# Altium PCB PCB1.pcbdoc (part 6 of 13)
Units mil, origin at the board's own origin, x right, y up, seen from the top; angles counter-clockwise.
Board outline 5895.51 x 5895.51 mil, 8 copper layers (Top Layer, L2_GND1, L3_SIG1, L4_GND2, L5_PWR, L6_SIG2, L7_GND3, Bottom Layer), stack 63.761 mil thick; 673 components, 558 nets, 2797 pads, 1861 vias.
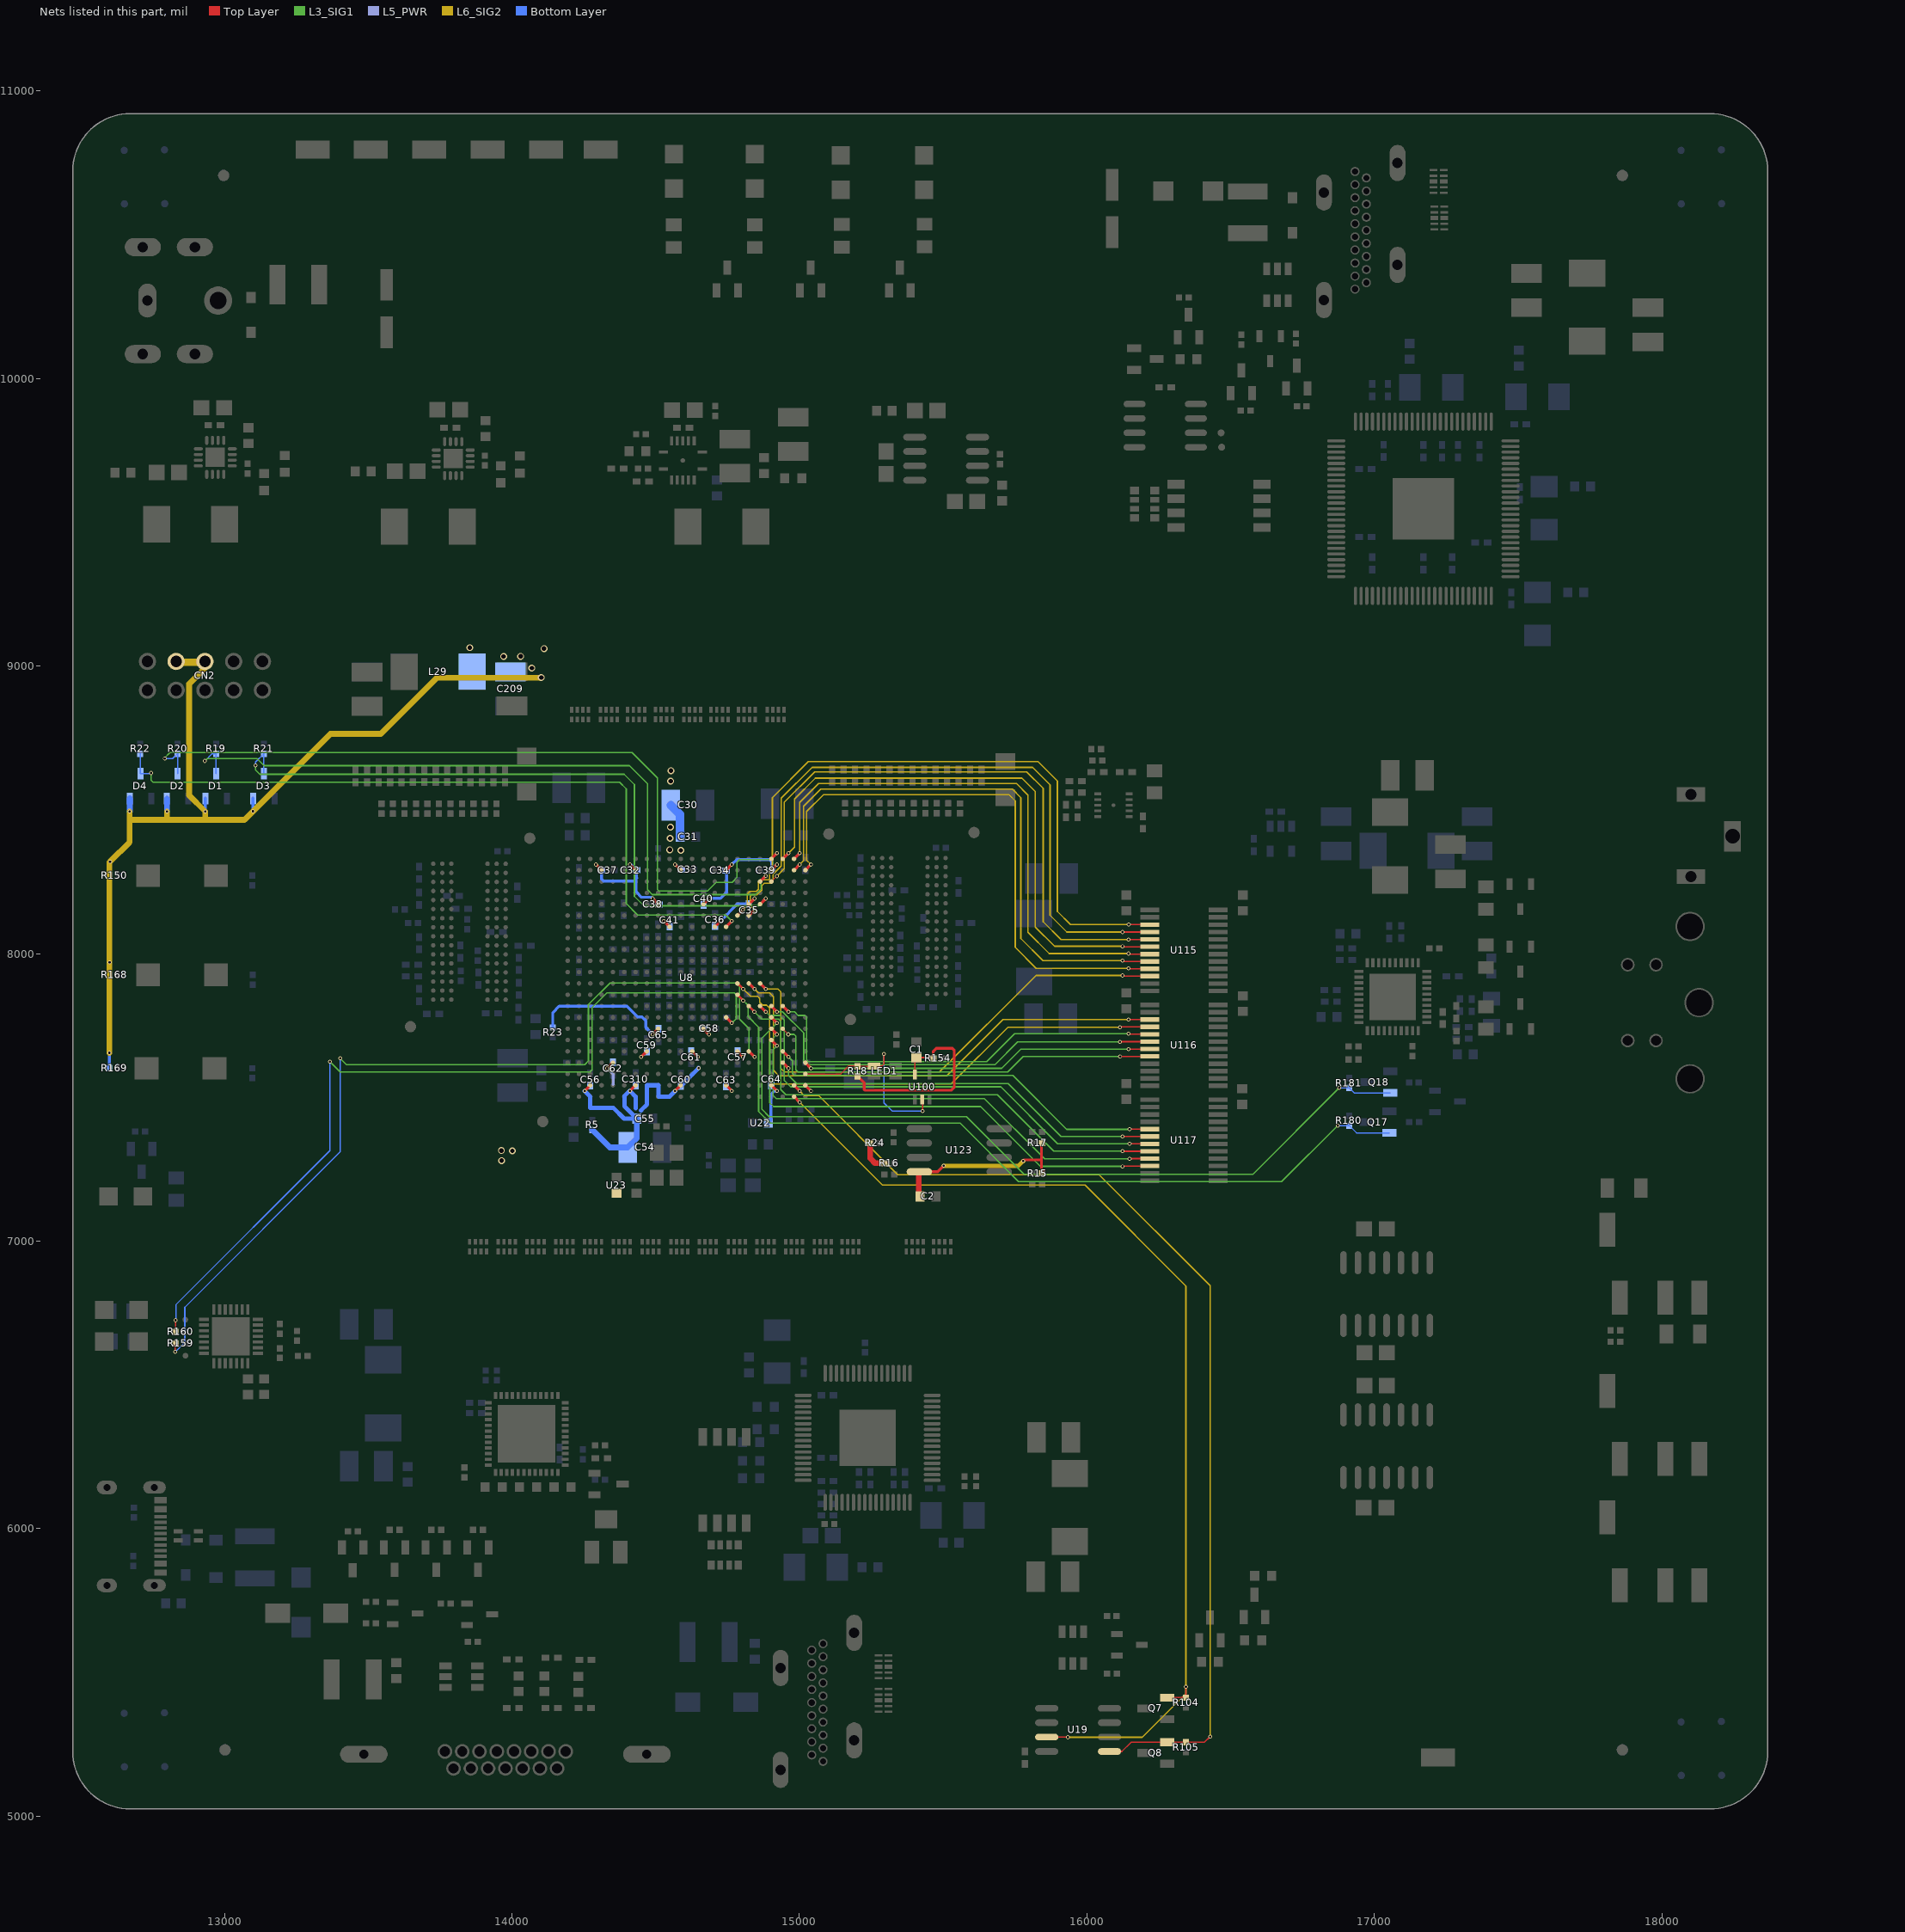
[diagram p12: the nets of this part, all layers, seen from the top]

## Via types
v1: diameter 23.62, hole 15.75, Top Layer to Bottom Layer, 621 vias
v2: diameter 13.8, hole 7.9, Top Layer to Bottom Layer, 567 vias
v3: diameter 13.78, hole 7.87, Top Layer to Bottom Layer, 529 vias
v4: diameter 13.78, hole 7.9, Top Layer to Bottom Layer, 114 vias
v5: diameter 15.75, hole 7.87, Top Layer to Bottom Layer, 16 vias
v6: diameter 24, hole 12, Top Layer to Bottom Layer, 10 vias
v7: diameter 11.81, hole 7.87, Top Layer to Bottom Layer, 4 vias

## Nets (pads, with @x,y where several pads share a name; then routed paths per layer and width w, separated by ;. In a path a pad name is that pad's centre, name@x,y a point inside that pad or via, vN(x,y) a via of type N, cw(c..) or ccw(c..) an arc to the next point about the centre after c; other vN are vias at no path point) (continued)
FPGA_3V3: C1.2 C2.2 C30.2 C31.2 C32.2 C33.2 C34.2 C35.2 C36.2 C37.2 C38.2 C39.2 C40.2 C41.2 C54.2 C55.2 C56.2 C57.2 C58.2 C59.2 C60.2 C61.2 C62.2 C63.2 C64.2 C65.2 C209.2 C310.2 CN2.4 CN2.6 D1.2 D2.2 D3.2 D4.2 L29.2 R5.2 R15.2 R16.2 R17.2 R18.1 R23.2 R24.2 R150.2 R154.1 R168.2 R169.2 U8.AA3 U8.AA7 U8.AA11 U8.AA15 U8.AA19 U8.AA22 U8.B4 U8.B7 U8.B11 U8.B15 U8.B19 U8.E9 U8.E13 U8.E17 U8.G10 U8.G14 U8.T9 U8.T13 U8.V8 U8.V12 U8.V16 U8.W5 U22.1 U23.1 U100.5 U123.8 | length 8780.3
  Top Layer w4.7: U100.5@15401.77,7579.31 15401.77,7632.85 C1.2@15407.36,7638.44 15462.88,7638.44 R154.1@15465.32,7636
  Top Layer w10: v2(14253.04,7522.32) U8.AA3@14272.71,7542 ; v2(14292.41,8309.69) U8.B4@14312.08,8290.01 ; v2(14331.79,7601.05) U8.W5@14351.46,7620.73 ; v2(14410.52,7522.32) U8.AA7@14430.19,7542 ; v2(14410.52,8309.69) U8.B7@14430.19,8290.01 ; v2(14449.89,7640.42) U8.V8@14469.56,7660.1 ; v2(14489.26,7719.16) U8.T9@14508.93,7738.84 ; v2(14489.26,8191.57) U8.E9@14508.93,8171.9 ; v2(14528.63,8112.84) U8.G10@14548.3,8093.16 ; v2(14567.99,7522.32) U8.AA11@14587.66,7542 ; v2(14567.99,8309.69) U8.B11@14587.66,8290.01 ; U8.V12@14627.06,7660.1 v2(14646.74,7640.42) ; U8.T13@14666.41,7738.84 v2(14686.09,7719.16) ; U8.E13@14666.41,8171.9 v2(14686.09,8191.57) ; U8.G14@14705.78,8093.16 v2(14725.46,8112.84) ; U8.AA15@14745.16,7542 v2(14764.84,7522.32) ; U8.B15@14745.16,8290.01 v2(14764.84,8309.69) ; U8.V16@14784.52,7660.1 v2(14804.2,7640.42) ; U8.E17@14823.89,8171.9 v2(14843.57,8191.57) ; U8.AA19@14902.63,7542 v2(14922.31,7522.32) ; U8.B19@14902.63,8290.01 v2(14922.31,8309.69) ; U8.AA22@15020.76,7542 v2(15040.44,7522.32) ; R18.1@15202.36,7573.96 15225.36,7550.96 15225.36,7527 15227.36,7525 15528.36,7525 15538.36,7535 15538.36,7665 15532.36,7671 15476.36,7671 15465.32,7659.96 R154.1@15465.32,7636 ; U123.8@15436.86,7241 15480.58,7241 v3(15501.56,7261.98) ; v3(15778.58,7278.63) 15782.66,7282.72 15842.05,7282.72 ; R15.2@15842.05,7233.31 15842.05,7282.72 ; R17.2@15842.05,7339.55 15842.05,7282.72
  Top Layer w20: R24.2@15246.18,7340.72 15246.18,7288.26 15263.23,7271.21 R16.2@15296.02,7271.21 ; U123.8@15413.41,7236.59 15415.59,7234.41 C2.2@15415.59,7155.27
  L5_PWR w10: v2(14331.79,7601.05) 14352.36,7580.48 14352.36,7545
  L6_SIG2 w15: v3(15501.56,7261.98) 15761.93,7261.98 v3(15778.58,7278.63)
  L6_SIG2 w20: v3(12600.44,7654.73) 12600.44,8317.76 v3(12602.49,8319.81) 12670.62,8387.94 12670.62,8465 ; v3(12670.62,8494.22) 12670.62,8465 ; v3(12800.32,8493.87) 12800.32,8465 ; CN2.6@12932.36,9016 12932.36,9013.28 12932.36,8993 12877.36,8938 12877.36,8550.4 v3(12933.54,8494.22) 12933.54,8465 ; v1(14102.24,8959.68) 13740.04,8959.68 13544.36,8764 13368.88,8764 v3(13099.8,8494.92) 13069.88,8465 12933.54,8465 ; 12670.62,8465 12800.32,8465 ; 12800.32,8465 12933.54,8465
  L6_SIG2 w25: CN2.4@12831.52,9012.62 12832.18,9013.28 12932.36,9013.28 CN2.6@12933.83,9013.28
  Bottom Layer w6: v2(14253.04,7522.32) 14271.22,7540.5 C56.2@14272.62,7540.5 ; v2(14292.41,8309.69) 14294.21,8309.69 C37.2@14312.9,8291 ; v2(14331.79,7601.05) 14331.79,7602.52 C62.2@14350.99,7621.72 ; v2(14410.52,7522.32) 14411.14,7522.32 C310.2@14430.36,7541.54 ; v2(14410.52,8309.69) 14416.13,8309.69 C32.2@14434.82,8291 ; v2(14449.89,7640.42) 14450.24,7640.42 C59.2@14469.36,7659.54 ; v2(14489.26,7719.16) 14508.56,7738.46 C65.2@14509.36,7738.46 ; v2(14489.26,8191.57) 14491.25,8191.57 C38.2@14511.82,8171 ; v2(14528.63,8112.84) 14545.66,8095.81 C41.2@14545.66,8091.87 ; v2(14567.99,7522.32) 14570.32,7522.32 C60.2@14587.91,7539.91 ; v2(14567.99,8309.69) 14571.21,8309.69 C33.2@14588.9,8292 ; C61.2@14623.5,7661.35 14625.81,7661.35 v2(14646.74,7640.42) ; C58.2@14664.9,7737 14668.25,7737 v2(14686.09,7719.16) ; C40.2@14666.73,8169.77 14666.73,8172.22 v2(14686.09,8191.57) ; C36.2@14706.36,8095.54 14708.16,8095.54 v2(14725.46,8112.84) ; C34.2@14746.82,8288 14746.82,8291.67 v2(14764.84,8309.69) ; C63.2@14747.36,7541.54 14764.84,7524.06 v2(14764.84,7522.32) ; C57.2@14783.36,7660.46 14784.16,7660.46 v2(14804.2,7640.42) ; C35.2@14824.46,8172.46 v2(14843.57,8191.57) ; C64.2@14902.36,7541.54 14903.09,7541.54 v2(14922.31,7522.32) ; C39.2@14903.82,8291.2 v2(14922.31,8309.69)
  Bottom Layer w10: v3(12600.44,7654.73) 12600.59,7654.57 R169.2@12600.59,7600.83 ; v3(12600.89,7969.07) 12601.35,7968.61 R168.2@12601.35,7923.85 ; R150.2@12601.79,8270.25 12601.79,8319.11 v3(12602.49,8319.81) ; v3(12933.54,8494.22) 12933.89,8494.57 D1.2@12933.89,8540.62 ; D3.2@13099.1,8540.62 13099.1,8495.63 v3(13099.8,8494.92) ; R23.2@14142.36,7743.04 14142.36,7795 14164.36,7817 14400.36,7817 14437.36,7780 14452.36,7780 14465.36,7767 14465.36,7743.06 v2(14489.26,7719.16) ; C37.2@14311.9,8290 14311.9,8259.46 14319.36,8252 14424.36,8252 14432.25,8259.9 ; C32.2@14434.82,8291 14432.99,8289.18 14432.99,8264.28 14434.82,8262.46 14432.25,8259.9 ; v2(14489.26,8191.57) 14484.83,8196 14450.36,8196 14432.25,8214.1 14432.25,8259.9 ; v2(14686.09,8191.57) 14686.52,8192 14725.36,8192 14746.82,8213.46 C34.2@14746.82,8288 ; v2(14725.46,8112.84) 14725.46,8113.1 14784.82,8172.46 C35.2@14824.36,8172.46 ; v2(14764.84,8309.69) 14782.15,8327 14896.36,8327 14903.82,8319.54 14903.82,8291.2 C39.2@14903.82,8289 ; U22.1@14892.21,7411 14901.36,7420.15 14901.36,7511 14912.68,7522.32 v2(14922.31,7522.32)
  Bottom Layer w15: v2(14253.04,7522.32) 14272.36,7503 14272.36,7464 14352.36,7464 14390.36,7426 C55.2@14434.8,7426 14391.36,7469.44 14391.36,7505 14408.68,7522.32 v2(14410.52,7522.32) 14430.36,7502.48 14430.36,7462 ; 14449.36,7455 14469.36,7475 14469.36,7542 14509.36,7542 14509.36,7504 14510.36,7503 14548.67,7503 v2(14567.99,7522.32) ; C60.2@14587.91,7539.91 14649.36,7601.35 v3(14649.36,7602)
  Bottom Layer w20: v3(12670.62,8494.22) 12670.96,8494.55 D4.2@12670.96,8539.64 ; D2.2@12799.96,8538.97 12799.96,8494.24 v3(12800.32,8493.87) ; R5.2@14279.71,7386.93 14340.64,7326 C54.2@14402.62,7326 14434.8,7358.18 C55.2@14434.8,7426
  Bottom Layer w30: C30.2@14552.62,8516 14584.8,8483.82 C31.2@14584.8,8406
  other v1: 13964.36,7280 14001.36,7314 13963.36,7315 14587.36,8359 14549.36,8361 14550.36,8401 14551.36,8440 14552.36,8600 14553.36,8636 14069.36,8993 13971.16,9033.22 14030.53,9033.67 14111.83,9060.62 13853.32,9063.82
FPGA_27M_OUT: U8.U19 U117.9 | length 1608.4
  Top Layer w4.7: v3(16148.36,7286) 16149.38,7287.02 U117.9@16218.36,7287.02
  Top Layer w10: U8.U19@14902.63,7699.47 v2(14922.31,7679.79)
  L3_SIG1 w5: v2(14922.31,7679.79) 14908.36,7665.84 14908.36,7507 14919.36,7496 15643.36,7496 15853.36,7286 v3(16148.36,7286)
FPGA_ADV7393_HS: U8.F17 U115.4 | length 2319.8
  Top Layer w4.7: v3(16123.36,8075) U115.4@16218.33,8075
  Top Layer w10: U8.F17@14823.89,8132.53 v2(14843.57,8152.21)
  L6_SIG2 w5: v2(14843.57,8152.21) 14829.51,8166.27 14829.51,8199.88 14834.51,8204.88 14852.92,8204.88 14869.06,8221.02 14869.06,8236.6 14877.49,8245.03 14902.27,8245.03 14907.96,8250.71 14907.96,8275.64 14937.06,8304.74 14937.06,8540.19 15044.4,8647.52 15810.9,8647.52 15871.79,8586.63 15871.79,8133.42 15930.21,8075 v3(16123.36,8075)
FPGA_ADV7393_P0: U8.C19 U115.5 | length 2121.9
  Top Layer w4.7: U8.C19@14902.86,8251.05 14921.2,8269.39 v3(14921.35,8269.39) ; v4(16144.36,8049.15) 16218.13,8049.15 U115.5@16218.36,8049.38
  L6_SIG2 w5: v3(14921.35,8269.39) 14947.69,8295.73 14947.69,8526.31 15053.69,8632.31 15790.74,8632.31 15848.03,8575.02 15848.03,8111.06 15909.94,8049.15 v4(16144.36,8049.15)
FPGA_ADV7393_P1: U8.A20 U115.6 | length 2009.4
  Top Layer w4.7: v4(16123.36,8025.43) 16124.99,8023.79 U115.6@16218.36,8023.79
  Top Layer w10: U8.A20@14942,8329.4 v2(14961.68,8349.07)
  L6_SIG2 w5: v2(14961.68,8349.07) 14983.26,8370.65 14983.26,8537.76 15055.71,8610.21 15773.7,8610.21 15820.25,8563.66 15820.25,8092.62 15887.44,8025.43 v4(16123.36,8025.43)
FPGA_ADV7393_P2: U8.A21 U115.7 | length 1974.2
  Top Layer w4.7: v4(16144.36,8000.35) 16146.5,7998.21 U115.7@16218.36,7998.21
  Top Layer w10: U8.A21@14981.36,8329.4 v2(15001.04,8349.07)
  L6_SIG2 w5: v2(15001.04,8349.07) 15001.04,8525.31 15067.14,8591.41 15755.07,8591.41 15794.97,8551.51 15794.97,8074.06 15868.68,8000.35 v4(16144.36,8000.35)
FPGA_ADV7393_P3: U8.B21 U115.8 | length 1999.8
  Top Layer w4.7: v4(16123.36,7975.47) 16126.22,7972.61 U115.8@16218.36,7972.61
  Top Layer w10: U8.B21@14981.36,8290.01 v2(15001.04,8309.69)
  L6_SIG2 w5: v2(15001.04,8309.69) 15014.25,8322.9 15014.25,8512.17 15074.07,8571.99 15740.72,8571.99 15770.13,8542.57 15770.13,8052.78 15847.45,7975.47 v4(16123.36,7975.47)
FPGA_ADV7393_P4: U8.B22 U115.9 | length 1985.5
  Top Layer w4.7: v4(16144.66,7948.74) 16146.38,7947.02 U115.9@16218.36,7947.02
  Top Layer w10: U8.B22@15020.76,8290.01 v2(15040.44,8309.69)
  L6_SIG2 w5: v2(15040.44,8309.69) 15025.41,8324.72 15025.41,8494.52 15083.78,8552.89 15729.2,8552.89 15750.96,8531.13 15750.96,8021.45 15823.67,7948.74 v4(16144.66,7948.74)
FPGA_ADV7393_P5: U8.M18 U115.10 | length 1778.9
  Top Layer w4.7: v3(16123.36,7924) 16125.93,7921.43 U115.10@16218.36,7921.43
  Top Layer w10: U8.M18@14863.26,7896.3 v2(14882.94,7876.62)
  L6_SIG2 w5: v2(14882.94,7876.62) 14925.74,7876.62 14935.36,7867 14935.36,7601 14948.36,7588 15487.36,7588 15823.36,7924 v3(16123.36,7924)
FPGA_ADV7393_P6: U8.M17 U116.3 | length 1758.9
  Top Layer w4.7: v3(16144.36,7771) 16144.8,7770.56 U116.3@16218.36,7770.56
  Top Layer w10: U8.M17@14823.89,7896.3 v2(14843.57,7876.62)
  L6_SIG2 w5: v2(14843.57,7876.62) 14857.19,7863 14896.36,7863 14909.36,7850 14909.36,7594 14928.36,7575 15512.36,7575 15708.36,7771 v3(16144.36,7771)
FPGA_ADV7393_P7: U8.M16 U116.4 | length 1816
  Top Layer w4.7: v3(16114.36,7744) 16115.33,7744.97 U116.4@16218.36,7744.97
  Top Layer w7.9: U8.M16@14784.52,7896.3 14803.82,7877 v3(14804.36,7877)
  L6_SIG2 w5: v3(14804.36,7877) 14830.36,7851 14855.36,7851 14862.36,7844 14862.36,7831 14872.36,7821 14886.36,7821 14896.36,7811 14896.36,7560 14910.36,7546 15527.36,7546 15725.36,7744 v3(16114.36,7744)
FPGA_ADV7393_P8: U8.P20 U116.5 | length 1485.2
  Top Layer w4.7: v3(16144.36,7721) 16145.98,7719.38 U116.5@16218.36,7719.38
  Top Layer w10: U8.P20@14942,7817.57 v2(14961.68,7797.9)
  L3_SIG1 w5: v2(14961.68,7797.9) 14983.46,7797.9 14988.36,7793 14988.36,7792 14995.36,7785 15019.36,7785 15025.36,7779 15025.36,7630.04 15031.4,7624 15651.36,7624 15748.36,7721 v3(16144.36,7721)
FPGA_ADV7393_P9: U8.P19 U116.6 | length 1492.8
  Top Layer w4.7: v3(16114.36,7693) 16115.15,7693.79 U116.6@16218.36,7693.79
  Top Layer w10: U8.P19@14902.63,7817.57 v2(14922.31,7797.9)
  L3_SIG1 w5: v2(14922.31,7797.9) 14941.46,7797.9 15015.46,7723.9 15015.46,7621.9 15023.36,7614 15680.36,7614 15759.36,7693 v3(16114.36,7693)
FPGA_ADV7393_P10: U8.W22 U116.7 | length 1233.6
  Top Layer w4.7: v3(16144.36,7668) 16218.15,7668 U116.7@16218.36,7668.21
  Top Layer w10: U8.W22@15020.76,7620.73 v2(15040.44,7601.05)
  L3_SIG1 w5: v2(15040.44,7601.05) 15703.41,7601.05 15770.36,7668 v3(16144.36,7668)
FPGA_ADV7393_P11: U8.T20 U116.8 | length 1430.3
  Top Layer w4.7: U8.T20@14942,7738.84 14961.36,7719.48 v3(14961.36,7719) ; v3(16115.36,7642) 16115.97,7642.61 U116.8@16218.36,7642.61
  L3_SIG1 w5: v3(14961.36,7719) 14981.36,7719 14987.36,7713 14987.36,7596 14995.36,7588 15724.36,7588 15778.36,7642 v3(16115.36,7642)
FPGA_ADV7393_P12: U8.V20 U117.5 | length 1413.8
  Top Layer w4.7: v3(16148.36,7389) 16148.74,7389.38 U117.5@16218.36,7389.38
  Top Layer w10: U8.V20@14942,7660.1 v2(14961.68,7640.42)
  L3_SIG1 w5: v2(14961.68,7640.42) 14975.36,7626.74 14975.36,7584 14983.36,7576 15742.36,7576 15929.36,7389 v3(16148.36,7389)
FPGA_ADV7393_P13: U8.W20 U117.6 | length 1397.1
  Top Layer w4.7: v3(16123.36,7364) 16123.57,7363.79 U117.6@16218.36,7363.79
  Top Layer w10: U8.W20@14942,7620.73 v2(14961.68,7601.05)
  L3_SIG1 w5: v2(14961.68,7601.05) 14961.68,7576.68 14990.36,7548 15726.36,7548 15910.36,7364 v3(16123.36,7364)
FPGA_ADV7393_P14: U8.P18 U117.7 | length 1676.7
  Top Layer w4.7: v3(16148.36,7339) 16149.15,7338.21 U117.7@16218.36,7338.21
  Top Layer w10: U8.P18@14863.26,7817.57 v2(14882.94,7797.9)
  L3_SIG1 w5: v2(14882.94,7797.9) 14895.84,7785 14931.36,7785 14947.36,7769 14947.36,7559 14969.36,7537 15700.36,7537 15898.36,7339 v3(16148.36,7339)
FPGA_ADV7393_P15: U8.P17 U117.8 | length 1742.5
  Top Layer w4.7: v3(16123.36,7313) 16123.75,7312.61 U117.8@16218.36,7312.61
  Top Layer w7.9: U8.P17@14823.89,7817.57 14843.36,7798.11 v3(14843.36,7798)
  L3_SIG1 w5: v3(14843.36,7798) 14869.36,7772 14927.36,7772 14935.36,7764 14935.36,7527 14953.36,7509 15688.36,7509 15884.36,7313 v3(16123.36,7313)
FPGA_ADV7393_RESET: U8.T19 U117.10 | length 1689.5
  Top Layer w4.7: v3(16123.36,7260) 16124.79,7261.43 U117.10@16218.36,7261.43
  Top Layer w10: U8.T19@14902.63,7738.84 v2(14922.31,7719.16)
  L3_SIG1 w5: v2(14922.31,7719.16) 14897.36,7694.21 14897.36,7481 14910.36,7468 15630.36,7468 15838.36,7260 v3(16123.36,7260)
FPGA_ADV7393_SCL: Q18.2 R181.1 U8.R19 | length 2759.7
  Top Layer w10: U8.R19@14902.63,7778.2 v2(14922.31,7758.52)
  L3_SIG1 w5: v2(14922.31,7758.52) 14869.36,7705.57 14869.36,7459 14895.36,7433 15581.36,7433 15781.36,7233 16577.36,7233 v3(16877.36,7533)
  Bottom Layer w4.7: v3(16877.36,7533) 16912.32,7533 16929.72,7515.6 Q18.2@17054.73,7515.6
FPGA_ADV7393_SDA: Q17.2 R180.1 U8.N16 | length 2822.1
  Top Layer w7.9: U8.N16@14784.52,7856.94 14804.36,7837.11 v3(14804.36,7837)
  L3_SIG1 w5: v3(14804.36,7837) 14821.36,7820 14821.36,7781 14858.36,7744 14858.36,7451.1 14899.46,7410 15559.36,7410 15762.36,7207 16677.36,7207 v3(16872.36,7402)
  Bottom Layer w4.7: v3(16872.36,7402) R180.1@16912.36,7401.96 16937.72,7376.6 Q17.2@17051.73,7376.6
FPGA_ADV7393_VS: U8.F16 U115.3 | length 2354.3
  Top Layer w4.7: v3(16145.36,8101) 16217.92,8101 U115.3@16218.36,8100.56
  Top Layer w10: U8.F16@14784.52,8132.53 v2(14804.2,8152.21)
  L6_SIG2 w5: v2(14804.2,8152.21) 14818.72,8166.73 14818.72,8207.45 14827.61,8216.34 14850.01,8216.34 ; 14850.06,8216.39 14857.74,8224.07 14857.74,8248.32 14865.64,8256.22 14894.13,8256.22 14896.74,8258.83 14896.74,8297.2 14906.02,8306.49 14906.02,8542.47 15030.83,8667.29 15830.05,8667.29 15897.26,8600.07 15897.26,8146.86 15943.12,8101 v3(16145.36,8101)
FPGA_DONE: LED1.4 R18.2 U8.Y22 U100.2 | length 680.9
  Top Layer w4.7: U8.Y22@15020.76,7581.35 15143.71,7581.35 15171.36,7609 15201.4,7609 R18.2@15202.36,7608.04 15259.28,7608.04 LED1.4@15259.96,7608.72 15287.07,7608.72 15294.36,7616 v3(15294.36,7651) ; U100.2@15427.36,7492.69 15428.36,7491.69 v3(15428.36,7452)
  Bottom Layer w4.7: v3(15294.36,7651) 15294.36,7481 15323.36,7452 v3(15428.36,7452)
FPGA_DVI_SCL: Q8.2 R105.1 U8.AA21 U19.1 | length 3675.4
  Top Layer w4.7: U19.1@16078.46,5225.41 16121.77,5225.41 16154.36,5258 16278.49,5258 Q8.2@16278.68,5257.81 16343.95,5257.81 R105.1@16344.31,5257.45 16408.81,5257.45 v4(16428.36,5277)
  Top Layer w10: U8.AA21@14981.36,7542 v2(15001.04,7522.32)
  L6_SIG2 w5: v2(15001.04,7522.32) 15016.36,7507 15066.36,7507 15342.36,7231 16042.36,7231 16428.36,6845 v4(16428.36,5277)
FPGA_DVI_SDA: Q7.2 R104.1 U8.AB21 U19.7 | length 3704.4
  Top Layer w4.7: U19.7@15860.16,5275.41 15933.95,5275.41 v3(15934.36,5275) ; Q7.2@16278.68,5412.81 16278.98,5412.5 16344.36,5412.5 v4(16344.36,5451)
  Top Layer w10: U8.AB21@14981.36,7502.6 v2(15001.04,7482.92)
  L6_SIG2 w5: v2(15001.04,7482.92) 15288.96,7195 15993.36,7195 16344.36,6844 v4(16344.36,5451) 16344.36,5427 16192.36,5275 v3(15934.36,5275)
FPGA_RXD: R160.2 U8.R15 | length 2964.3
  Top Layer w4.7: R160.2@12830.65,6684.8 v3(12830.65,6725)
  Top Layer w10: U8.R15@14745.16,7778.2 v2(14764.84,7758.52)
  L3_SIG1 w5: v3(13367.36,7624) 13403.16,7588.2 14271.46,7588.2 14279.36,7596.1 14279.36,7812 14330.36,7863 14773.36,7863 14780.36,7856 14780.36,7774.04 v2(14764.84,7758.52)
  Bottom Layer w4.7: v3(12830.65,6725) 12831.36,6725.71 12831.36,6779 13367.36,7315 v3(13367.36,7624)
FPGA_TCK: D4.3 R22.2 U8.G15 | length 2616.2
  Top Layer w10: U8.G15@14745.16,8093.16 v2(14764.84,8112.84)
  L3_SIG1 w5: v4(12745.36,8628) 12745.36,8602.63 12751.96,8596.02 14374.62,8596.02 14397.67,8572.97 14397.67,8174.13 14437.53,8134.27 14743.41,8134.27 v2(14764.84,8112.84)
  Bottom Layer w4.7: R22.2@12707.36,8695.29 12708.36,8694.29 D4.3@12708.36,8626.36 12743.72,8626.36 v4(12745.36,8628)
FPGA_TDI: D3.3 R21.2 U8.E18 | length 2375
  Top Layer w10: U8.E18@14863.26,8171.9 v2(14882.94,8191.57)
  L3_SIG1 w5: v3(13108.36,8654) 13108.36,8638.48 13123.01,8623.83 14390.33,8623.83 14426.29,8587.86 14426.29,8198.8 14459.02,8166.07 14857.43,8166.07 v2(14882.94,8191.57)
  Bottom Layer w4.7: v3(13108.36,8654) 13108.36,8666.29 R21.2@13137.36,8695.29 D3.3@13137.36,8625.69
FPGA_TDO: D2.3 R20.2 U8.A19 | length 2801.6
  Top Layer w10: U8.A19@14902.63,8329.4 v2(14922.31,8349.07)
  L3_SIG1 w5: v3(12792.36,8678) 12792.36,8680.39 12810.97,8699 14417.77,8699 14505.81,8610.96 14505.81,8222.85 14510.99,8217.67 14680.28,8217.67 14710.43,8247.82 14766.15,8247.82 14782.9,8264.56 14782.9,8317.24 14792.03,8326.37 14899.61,8326.37 v2(14922.31,8349.07)
  Bottom Layer w4.7: v3(12792.36,8678) 12820.07,8678 R20.2@12837.36,8695.29 D2.3@12837.36,8625.69
FPGA_TMS: D1.3 R19.2 U8.C18 | length 2557.2
  Top Layer w10: U8.C18@14863.26,8250.65 v2(14882.94,8270.32)
  L3_SIG1 w5: v3(12932.36,8670) 12940.94,8678.58 13113.77,8678.58 13138.66,8653.69 14408.6,8653.69 14471.48,8590.81 14471.48,8222 14488.53,8204.95 14846.91,8204.95 14866.4,8224.44 14866.4,8253.78 v2(14882.94,8270.32)
  Bottom Layer w4.7: v3(12932.36,8670) 12957.65,8695.29 R19.2@12971.03,8695.29 D1.3@12971.03,8625.69
FPGA_TXD: R159.2 U8.V17 | length 3219.2
  Top Layer w4.7: v3(12829.36,6615) 12829.36,6643.51 R159.2@12830.65,6644.8
  Top Layer w10: U8.V17@14823.89,7660.1 v2(14843.57,7640.42)
  L3_SIG1 w5: v3(13402.36,7636) 13424.36,7614 14253.36,7614 14266.36,7627 14266.36,7823 14341.36,7898 14779.36,7898 14791.36,7886 14791.36,7772 14824.36,7739 14824.36,7659.63 v2(14843.57,7640.42)
  Bottom Layer w4.7: v3(12829.36,6615) 12862.36,6648 12862.36,6770 13402.36,7310 v3(13402.36,7636)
